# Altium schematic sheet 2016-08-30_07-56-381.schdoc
size 403 x 140 mm; SheetNumber: 1; SheetTotal: 1
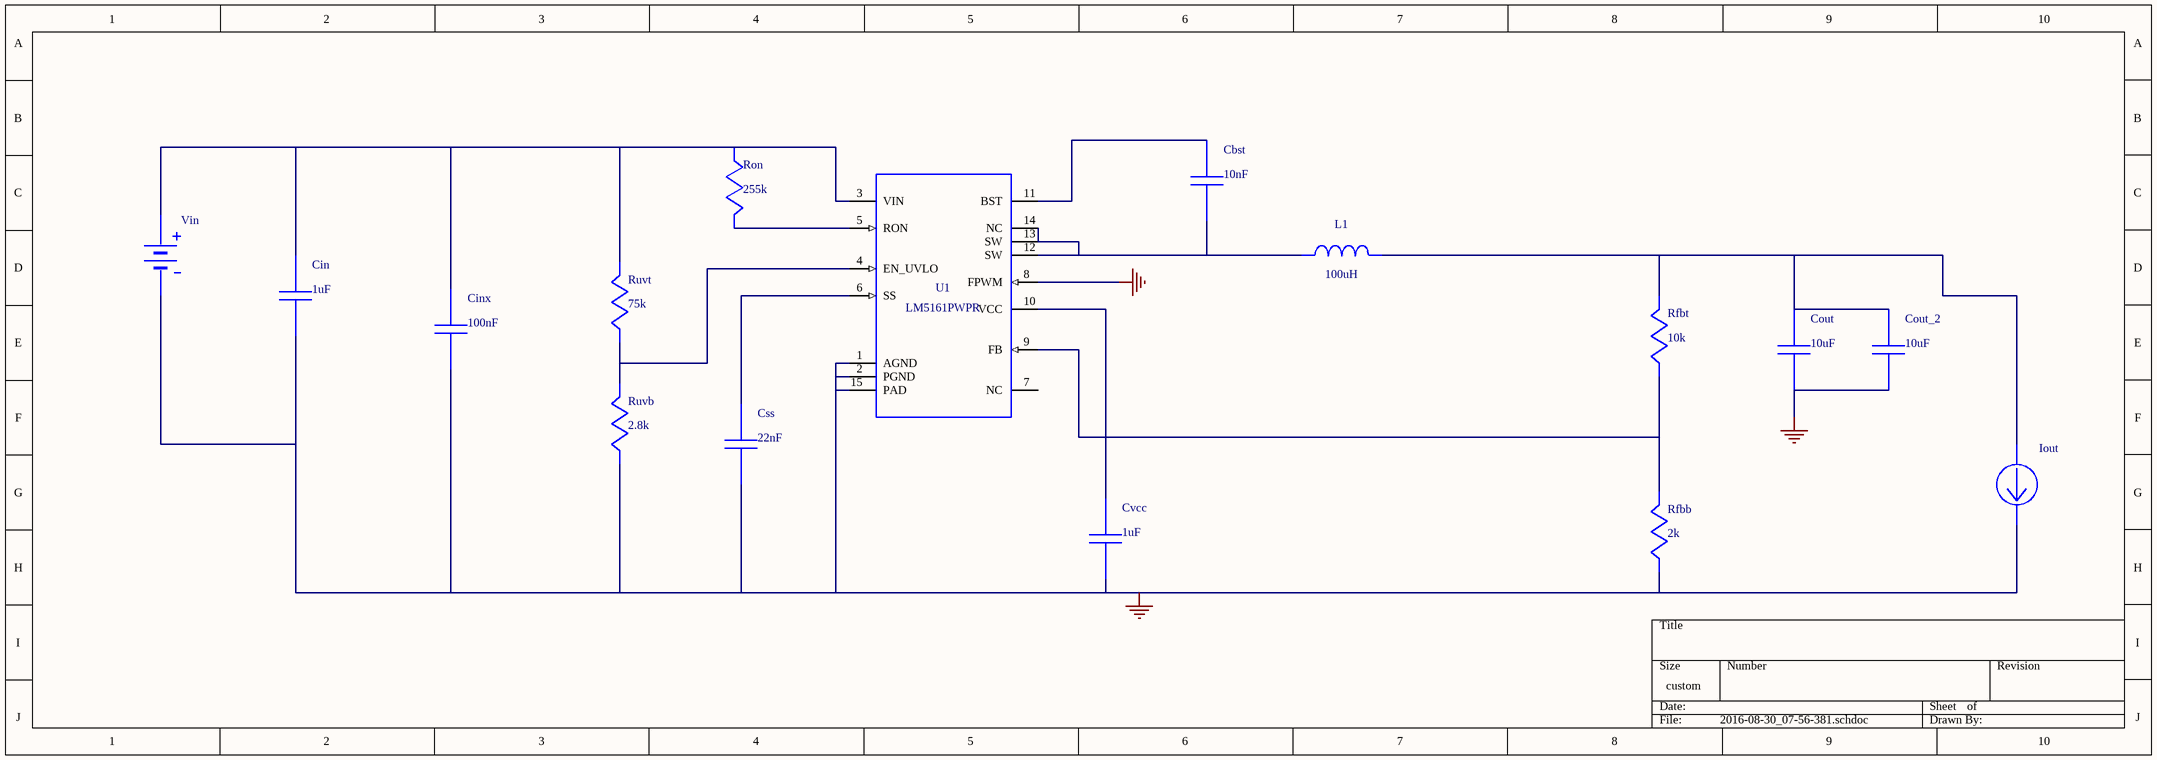
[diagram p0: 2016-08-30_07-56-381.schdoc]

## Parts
Cbst  value 10nF  (hidden comment: GRM188R71C103KA01D)
Cin  value 1uF  (hidden comment: GRM31CR72A105KA01L)
Cinx  value 100nF  (hidden comment: C0805C104K1RACTU)
Cout  value 10uF  (hidden comment: GRM21BR61C106KE15L)
Cout_2  value 10uF  (hidden comment: GRM21BR61C106KE15L)
Css  value 22nF  (hidden comment: C0603C223K4RACTU)
Cvcc  value 1uF  (hidden comment: GRM188R61C105KA93D)
Iout  WB_CURRENT_LOAD  (value not drawn)
L1  value 100uH  (hidden comment: SRR1260-101M)
Rfbb  value 2k  (hidden comment: ERJ-6ENF2001V)
Rfbt  value 10k  (hidden comment: ERJ-6ENF1002V)
Ron  value 255k  (hidden comment: ERJ-6ENF2553V)
Ruvb  value 2.8k  (hidden comment: ERJ-6ENF2801V)
Ruvt  value 75k  (hidden comment: ERJ-6ENF7502V)
U1  LM5161PWPR
Vin  WB_BATTERY  (value not drawn)

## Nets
0: Cin.2 Cinx.2 Cout.2 Cout_2.2 Css.2 Cvcc.1 Iout.2(-) Rfbb.2 Ruvb.2 U1.1(AGND) U1.2(PGND) U1.8(FPWM) U1.15(PAD) Vin.2(-)
NetCbst_1: Cbst.1 U1.11(BST)
NetCbst_2: Cbst.2 L1.1 U1.12(SW) U1.13(SW) U1.14(NC)
NetCin_1: Cin.1 Cinx.1 Ron.2 Ruvt.1 U1.3(VIN) Vin.1(+)
NetCout_1: Cout.1 Cout_2.1 Iout.1(+) L1.2 Rfbt.1
NetCss_1: Css.1 U1.6(SS)
NetCvcc_2: Cvcc.2 U1.10(VCC)
NetRfbb_1: Rfbb.1 Rfbt.2 U1.9(FB)
NetRon_1: Ron.1 U1.5(RON)
NetRuvb_1: Ruvb.1 Ruvt.2 U1.4(EN_UVLO)

Not connected (* = marked no-connect by the designer): U1 7(NC)

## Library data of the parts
Cbst = GRM188R71C103KA01D: GRM188R71C103KA0; Manufacturer Name: MuRata
Cin = GRM31CR72A105KA01L: GRM31CR72A105KA0; Manufacturer Name: MuRata
Cinx = C0805C104K1RACTU: Manufacturer Name: Kemet
Cout Cout_2 = GRM21BR61C106KE15L: GRM21BR61C106KE1; Manufacturer Name: MuRata
Css = C0603C223K4RACTU: Manufacturer Name: Kemet
Cvcc = GRM188R61C105KA93D: GRM188R61C105KA9; Manufacturer Name: MuRata
L1 = SRR1260-101M: Manufacturer Name: Bourns
Rfbb = ERJ-6ENF2001V: Manufacturer Name: Panasonic
Rfbt = ERJ-6ENF1002V: Manufacturer Name: Panasonic
Ron = ERJ-6ENF2553V: Manufacturer Name: Panasonic
Ruvb = ERJ-6ENF2801V: Manufacturer Name: Panasonic
Ruvt = ERJ-6ENF7502V: Manufacturer Name: Panasonic
U1 = LM5161PWPR: Manufacturer Name: Texas Instruments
